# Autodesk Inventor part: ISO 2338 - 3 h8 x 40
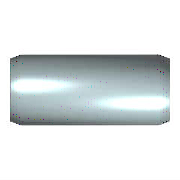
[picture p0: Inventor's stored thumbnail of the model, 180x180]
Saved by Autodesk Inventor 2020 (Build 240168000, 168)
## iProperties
Created: 2019-01
Part Number: ISO 2338 - 3 h8 x 40
Material: Nerezová ocel, austenitická
Description: Rovnoběžný kolík
Document SubType Name: Modeling
Standard: ISO 2338
Designer: doma
Standard Revision: Second edition 1997-11-01
Standards Organization: ISO
Language: cs-CZ
Size Designation: 3 h8 x 40
Categories: <MemberInstance><Categories><Category DisplayName="Spojovací materiál" InternalName="e4da775c-781d-43d5-af7c-5136215cf5a6" Mnemonic="FSTN"><Category DisplayName
Density: 8 g/cm^3
Appearance: Pololeštěná
IsCustomPart: 0
Author: doma
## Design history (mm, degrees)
sketch "Náčrt"
  geometry: C1 r 1.5 at (0, 0); 1 further point
  constraints: 1 centre point, 1 coincident
  dimensions: "d1" = 3 diameter of C1 (= NND)
extrude "Těleso" new body sketch "Náčrt" distance "d2" = 40 (= NLG); taper "d3" = 0 deg
chamfer "Náčrt2" distance "d8" = 0.5 (= PHH); stored, may be unused: angle "d9" = 15 deg (= FAWI), second distance "d12" = 0.5 (= PHH)
body "Solid1"
chamfer "Zkosení1" distance "d4" = 0.5 (= PHH); stored, may be unused: angle "d5" = 15 deg (= FAWI), second distance "d11" = 0.5 (= PHH)
other parameters: "NND" = 3 [user parameter; used in 1 equation term], "NLG" = 40 [user parameter; used in 1 equation term], "PHH" = 0.5 [user parameter; used in 4 equation terms], "FAWI" = 15 deg [user parameter; used in 2 equation terms], "d13" = 0, "d15" = 0, "d16" = 0, "KAH" = 0 [user parameter]
